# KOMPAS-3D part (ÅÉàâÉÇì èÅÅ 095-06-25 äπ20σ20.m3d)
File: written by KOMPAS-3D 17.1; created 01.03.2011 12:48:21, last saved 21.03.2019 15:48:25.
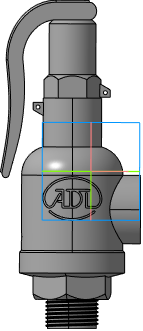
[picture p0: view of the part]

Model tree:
1. Операция без истории:1

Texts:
  Viktor2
